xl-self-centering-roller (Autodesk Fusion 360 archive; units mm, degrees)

design "XL SELF CENTERING ROLLER" references "XL ROLLER"
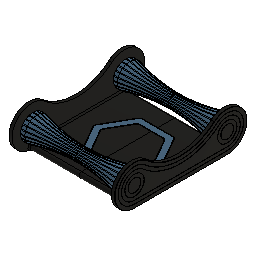
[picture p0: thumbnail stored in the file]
sketch "Sketch1" plane through (0, 0, 0) normal (1, 0, 0) x axis (0, 1, 0)
  line L1 (70, 4) -> (-70, 4)
  line L2 (70, -4) -> (70, 4)
  line L3 (-70, -4) -> (70, -4)
  line L4 (-70, 4) -> (-70, -4)
  line L5 (70, -4) -> (-70, 4)
  line L6 (-70, -4) -> (70, 4)
  line L7 (-104.641, 0) -> (-87.3205, 30)
  line L8 (-87.3205, -30) -> (-104.641, 0)
  line L9 (-52.6795, -30) -> (-87.3205, -30)
  line L10 (-35.359, 0) -> (-52.6795, -30)
  line L11 (-52.6795, 30) -> (-35.359, 0)
  line L12 (-87.3205, 30) -> (-52.6795, 30)
  line L13 (35.359, 0) -> (52.6795, 30)
  line L14 (52.6795, -30) -> (35.359, 0)
  line L15 (87.3205, -30) -> (52.6795, -30)
  line L16 (104.641, 0) -> (87.3205, -30)
  line L17 (87.3205, 30) -> (104.641, 0)
  line L18 (52.6795, 30) -> (87.3205, 30)
  line L19 (-52.6795, -30) -> (52.6795, -30)
  line L20 (35.359, 0) -> (-35.359, 0)
  line L21 (-82.7017, -22) -> (-87.3205, -30)
  line L22 (82.7017, -22) -> (-82.7017, -22)
  line L23 (87.3205, -30) -> (82.7017, -22)
  line L24 (-91.9393, -22) -> (91.9393, -22)
  line L25 (70, 0) -> (-70, 0)
  line L26 (0, -30) -> (0, 0)
  line L27 (0, -30) -> (0, -22)
  line L28 (-70, -22) -> (70, -22)
  line L29 (70, -30) -> (-70, -30)
  line L30 (70, -26) -> (70, 0)
  circle C1 centre (-70, 0) radius 4
  circle C2 centre (70, 0) radius 4
  circle C3 centre (70, 0) radius 5
  circle C4 centre (-70, 0) radius 5
  circle C5 centre (-70, 0) radius 30
  circle C6 centre (70, 0) radius 30
  arc A1 centre (-70, -26) radius 4 clockwise from (-70, -30) to (-70, -22)
  arc A2 centre (70, -26) radius 4 clockwise from (70, -22) to (70, -30)
  arc A3 centre (0, 81.2307) radius 77.2307 clockwise from (50.4161, 22.726) to (-50.4161, 22.726)
  point P6 (0, 0)
  point P1 (0, 0)
  point P7 (-70, 0)
  point P8 (70, 0)
  point P15 (-70, 0)
  point P22 (70, 0)
  point P27 (91.9393, -22)
  point P28 (-91.9393, -22)
  point P29 (-70, 0)
  point P31 (-70, 0)
  point P32 (70, 0)
  point P33 (0, 0)
  point P34 (0, -30)
  point P35 (0, -22)
  point P42 (0, -26)
  point P30 (70, 0)
  point P43 (70, 0)
  point P40 (70, -26)
  point P44 (70, -26)
  point P41 (-70, -26)
  point P46 (50.4161, 22.726)
  point P45 (-50.4161, 22.726)
  point P4 (70, -4)
  point P5 (-70, -4)
  horizontal L1
  perpendicular L1 L2
  parallel L1 L3
  parallel L2 L4
  coincident L5 P6
  coincident L6 P6
  coincident P1 P6
  midpoint L4 P7
  midpoint L2 P8
  tangent L1 C1
  coincident P7 P15
  coincident P8 P22
  horizontal L12
  horizontal L18
  parallel L15 L22
  parallel L17 L23
  parallel L7 L21
  coincident L16 P27
  coincident L8 P28
  parallel L22 L24
  collinear L22 L24
  concentric C1 C5
  tangent L9 C5
  concentric C2 C6
  tangent L15 C6
  coincident P29 P31
  coincident P22 P32
  coincident P6 P33
  midpoint L19 P34
  midpoint L24 P35
  tangent L28 A1
  tangent A1 L29
  parallel L28 L29
  tangent L29 A2
  tangent L28 A2
  midpoint L27 P42
  coincident P30 P43
  coincident P40 P44
  vertical L30
  collinear L22 L28
  collinear L19 L29
  vertical P29 P41
  coincident C6 P46
  coincident C5 P45
  tangent C5 A3
  tangent C6 A3
  tangent L1 A3
  dimension "d1" diameter C1 = 8 (= "d2")
  dimension "d2" diameter C2 = 8
  dimension "d3" distance P4 P5 = 140
  dimension "d4" distance L9 L12 = 60
  dimension "d5" distance L15 L18 = 60 (= "d4")
  dimension "d6" distance L19 L22 = 8
  dimension "d13" = 1
  dimension "d14" = 1
extrude "Extrude1" new body sketch "MirrorComponent3" profile of L9 L10 L14 L15 L19 L22 L24 C5 C6 L27 L28 A1 L29 A2 against normal blind 75
extrude "Extrude2" add sketch "MirrorComponent3" profile of L1 L2 L3 L4 C1 C2 L9 L10 L14 L15 L19 L20 L21 L22 L23 C3 C4 L24 C5 C6 L25 L27 L28 A1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 along normal blind 5
extrude "Extrude3" add sketch "MirrorComponent3" profile of L2 L4 C1 C2 against normal blind 6
extrude "Extrude19" add sketch "MirrorComponent3" profile of L1 L11 L13 L20 C5 C6 L25 A3 along normal blind 5
chamfer "Chamfer1" distance 0.6
sketch "Sketch2" plane through (5, 0, 0) normal (1, 0, 0) x axis (0, 1, 0)
  line L1 (63.8564, -25) -> (-63.8564, -25)
  line L2 (78.5788, -0.5) -> (64.7224, -24.5)
  line L3 (64.7224, 24.5) -> (78.5788, 0.5)
  line L4 (36.1436, 25) -> (63.8564, 25)
  line L5 (21.4212, 0.5) -> (35.2776, 24.5)
  line L6 (-20.5551, 0) -> (20.5551, 0)
  line L7 (-35.2776, 24.5) -> (-21.4212, 0.5)
  line L8 (-63.8564, 25) -> (-36.1436, 25)
  line L9 (-78.5788, 0.5) -> (-64.7224, 24.5)
  line L10 (-64.7224, -24.5) -> (-78.5788, -0.5)
  line L11 (-75.8653, 0) -> (-62.9326, 22.4)
  line L12 (-62.9326, -22.4) -> (-75.8653, 0)
  line L13 (-35.5662, -22.4) -> (-62.9326, -22.4)
  line L14 (62.9326, -22.4) -> (-35.5662, -22.4)
  line L15 (75.8653, 0) -> (62.9326, -22.4)
  line L16 (62.9326, 22.4) -> (75.8653, 0)
  line L17 (37.0674, 22.4) -> (62.9326, 22.4)
  line L18 (23.6728, -0.8) -> (37.0674, 22.4)
  line L19 (-20.5551, -2.6) -> (20.5551, -2.6)
  line L20 (-37.0674, 22.4) -> (-23.6728, -0.8)
  line L21 (-62.9326, 22.4) -> (-37.0674, 22.4)
  line L22 (-73.5559, 0) -> (-61.7779, 20.4)
  line L23 (-61.7779, -20.4) -> (-73.5559, 0)
  line L24 (-35.5662, -20.4) -> (-61.7779, -20.4)
  line L25 (61.7779, -20.4) -> (-35.5662, -20.4)
  line L26 (73.5559, 0) -> (61.7779, -20.4)
  line L27 (61.7779, 20.4) -> (73.5559, 0)
  line L28 (38.2221, 20.4) -> (61.7779, 20.4)
  line L29 (25.4049, -1.8) -> (38.2221, 20.4)
  line L30 (-20.5551, -4.6) -> (20.5551, -4.6)
  line L31 (-38.2221, 20.4) -> (-25.4049, -1.8)
  line L32 (-61.7779, 20.4) -> (-38.2221, 20.4)
  line L33 (70, -30) -> (-70, -30)
  arc A1 centre (-63.8564, -24) radius 1 clockwise from (-63.8564, -25) to (-64.7224, -24.5)
  arc A2 centre (63.8564, -24) radius 1 clockwise from (64.7224, -24.5) to (63.8564, -25)
  arc A3 centre (77.7128, 0) radius 1 clockwise from (78.5788, 0.5) to (78.5788, -0.5)
  arc A4 centre (63.8564, 24) radius 1 clockwise from (63.8564, 25) to (64.7224, 24.5)
  arc A5 centre (36.1436, 24) radius 1 clockwise from (35.2776, 24.5) to (36.1436, 25)
  arc A6 centre (20.5551, 1) radius 1 clockwise from (21.4212, 0.5) to (20.5551, 0)
  arc A7 centre (-20.5551, 1) radius 1 clockwise from (-20.5551, 0) to (-21.4212, 0.5)
  arc A8 centre (-36.1436, 24) radius 1 clockwise from (-36.1436, 25) to (-35.2776, 24.5)
  arc A9 centre (-63.8564, 24) radius 1 clockwise from (-64.7224, 24.5) to (-63.8564, 25)
  arc A10 centre (-77.7128, 0) radius 1 clockwise from (-78.5788, -0.5) to (-78.5788, 0.5)
  arc A11 centre (20.5551, 1) radius 3.6 clockwise from (23.6728, -0.8) to (20.5551, -2.6)
  arc A12 centre (-20.5551, 1) radius 3.6 clockwise from (-20.5551, -2.6) to (-23.6728, -0.8)
  arc A13 centre (20.5551, 1) radius 5.6 clockwise from (25.4049, -1.8) to (20.5551, -4.6)
  arc A14 centre (-20.5551, 1) radius 5.6 clockwise from (-20.5551, -4.6) to (-25.4049, -1.8)
  arc A15 centre (70, 0) radius 30 clockwise from (50.4161, 22.726) to (70, -30)
  arc A16 centre (-70, 0) radius 30 clockwise from (-70, -30) to (-50.4161, 22.726)
  arc A17 centre (0, 81.2307) radius 77.2307 clockwise from (50.4161, 22.726) to (-50.4161, 22.726)
  concentric A6 A11
  concentric A7 A12
  tangent A12 L20
  tangent L18 A11
  tangent A11 L19
  tangent L19 A12
  concentric A6 A13
  concentric A7 A14
  tangent A14 L31
  tangent A13 L30
  tangent L29 A13
  tangent L30 A14
sketch "Sketch3" plane through (0, 0, -22) normal (0, 0, 1) x axis (-1, 0, 0)
  line L1 (75, 70) -> (75, -70)
  line L2 (126.9615, 0) -> (100.9808, -45)
  line L3 (100.9808, 45) -> (126.9615, 0)
  line L4 (49.0192, 45) -> (100.9808, 45)
  line L5 (23.0385, 0) -> (49.0192, 45)
  line L6 (49.0192, -45) -> (23.0385, 0)
  line L7 (100.9808, -45) -> (49.0192, -45)
  line L8 (95.2073, 35) -> (115.4145, 0)
  line L9 (54.7927, 35) -> (95.2073, 35)
  line L10 (34.5855, 0) -> (54.7927, 35)
  line L11 (54.7927, -35) -> (34.5855, 0)
  line L12 (95.2073, -35) -> (54.7927, -35)
  line L13 (115.4145, 0) -> (95.2073, -35)
  line L14 (75, -70) -> (0, -70)
  line L15 (0, 70) -> (75, 70)
  line L16 (0, -70) -> (0, 70)
  point P12 (75, 0)
  midpoint L1 P12
  horizontal L7
  dimension "d23" distance L4 L7 = 90
  dimension "d24" = -10
extrude "Extrude5" cut sketch "Sketch3" profile of L1 L4 L5 L6 L7 L12 L10 L9 L11 against normal blind 2
fillet "Fillet2" radius 5
extrude "Extrude6" add sketch "MirrorComponent3" profile of L1 L3 C1 C2 C3 C4 against normal blind 1.4
chamfer "Chamfer3" distance 1.4
chamfer "Chamfer6" distance 0.4
chamfer "Chamfer10" distance 2
sketch "Sketch11" plane through (5, 0, 0) normal (1, 0, 0) x axis (0, 1, 0)
  line L1 (70, -29.6) -> (-70, -29.6)
  line L2 (70, -24.6) -> (-70, -24.6)
  line L3 (70, -19.6) -> (-70, -19.6)
  arc A1 centre (70, 0) radius 29.6 clockwise from (50.6772, 22.423) to (70, -29.6)
  arc A2 centre (0, 81.2307) radius 77.6307 clockwise from (50.6772, 22.423) to (-50.6772, 22.423)
  arc A3 centre (-70, 0) radius 29.6 clockwise from (-70, -29.6) to (-50.6772, 22.423)
  arc A4 centre (70, 0) radius 24.6 clockwise from (53.9412, 18.6353) to (70, -24.6)
  arc A5 centre (0, 81.2307) radius 82.6307 clockwise from (53.9412, 18.6353) to (-53.9412, 18.6353)
  arc A6 centre (-70, 0) radius 24.6 clockwise from (-70, -24.6) to (-53.9412, 18.6353)
  arc A7 centre (70, 0) radius 19.6 clockwise from (57.2052, 14.8476) to (70, -19.6)
  arc A8 centre (0, 81.2307) radius 87.6307 clockwise from (57.2052, 14.8476) to (-57.2052, 14.8476)
  arc A9 centre (-70, 0) radius 19.6 clockwise from (-70, -19.6) to (-57.2052, 14.8476)
  circle C1 centre (-70, 0) radius 14.6
  circle C2 centre (70, 0) radius 14.6
  circle C3 centre (-70, 0) radius 9.6
  circle C4 centre (70, 0) radius 9.6
  concentric A3 C1
  concentric A1 C2
  concentric C1 C3
  concentric C2 C4
  dimension "d145" = -5
  dimension "d146" = -10
  dimension "d148" distance A9 C1 = 5
  dimension "d149" distance A7 C2 = 5 (= "d148")
  dimension "d168" distance C1 C3 = 5
  dimension "d169" distance C2 C4 = 5
extrude "Extrude21" cut sketch "Sketch11" profile of L2 A6 A5 A4 L3 A9 A8 A7 C1 C2 C3 C4 against normal blind 0.4
mirror "Mirror1" mirrorStitchTolerance 0.1
sketch "Sketch1" plane through (0, 0, -24) normal (0, 0, 1) x axis (-1, 0, 0)
  line L1 (98.094, -45) -> (51.906, -45)
  line L2 (57.6795, -35) -> (92.3205, -35)
  line L3 (36.0289, -2.5) -> (53.3494, -32.5)
  line L4 (53.3494, 32.5) -> (36.0289, 2.5)
  line L5 (92.3205, 35) -> (57.6795, 35)
  line L6 (51.906, 45) -> (98.094, 45)
  line L7 (24.4819, 2.5) -> (47.5759, 42.5)
  line L8 (47.5759, -42.5) -> (24.4819, -2.5)
  line L9 (125.5181, -2.5) -> (102.4241, -42.5)
  line L10 (102.4241, 42.5) -> (125.5181, 2.5)
  line L11 (113.9711, 2.5) -> (96.6506, 32.5)
  line L12 (96.6506, -32.5) -> (113.9711, -2.5)
  line L13 (51.906, 45) -> (98.094, 45)
  line L14 (24.4819, 2.5) -> (47.5759, 42.5)
  line L15 (47.5759, -42.5) -> (24.4819, -2.5)
  line L16 (98.094, -45) -> (51.906, -45)
  line L17 (125.5181, -2.5) -> (102.4241, -42.5)
  line L18 (102.4241, 42.5) -> (125.5181, 2.5)
  line L19 (92.3205, 35) -> (57.6795, 35)
  line L20 (113.9711, 2.5) -> (96.6506, 32.5)
  line L21 (96.6506, -32.5) -> (113.9711, -2.5)
  line L22 (57.6795, -35) -> (92.3205, -35)
  line L23 (36.0289, -2.5) -> (53.3494, -32.5)
  line L24 (53.3494, 32.5) -> (36.0289, 2.5)
  line L25 (24.6551, 2.4) -> (47.7491, 42.4)
  line L26 (47.7491, -42.4) -> (24.6551, -2.4)
  line L27 (98.094, -44.8) -> (51.906, -44.8)
  line L28 (125.3449, -2.4) -> (102.2509, -42.4)
  line L29 (102.2509, 42.4) -> (125.3449, 2.4)
  line L30 (51.906, 44.8) -> (98.094, 44.8)
  line L31 (92.3205, 35.2) -> (57.6795, 35.2)
  line L32 (53.1762, 32.6) -> (35.8557, 2.6)
  line L33 (35.8557, -2.6) -> (53.1762, -32.6)
  line L34 (57.6795, -35.2) -> (92.3205, -35.2)
  line L35 (96.8238, -32.6) -> (114.1443, -2.6)
  line L36 (114.1443, 2.6) -> (96.8238, 32.6)
  line L37 (121.188, 0) -> (98.094, -40)
  line L38 (98.094, 40) -> (121.188, 0)
  line L39 (51.906, 40) -> (98.094, 40)
  line L40 (28.812, 0) -> (51.906, 40)
  line L41 (51.906, -40) -> (28.812, 0)
  line L42 (98.094, -40) -> (51.906, -40)
  arc A1 centre (51.906, -40) radius 5 clockwise from (51.906, -45) to (47.5759, -42.5)
  arc A2 centre (57.6795, -30) radius 5 clockwise from (57.6795, -35) to (53.3494, -32.5)
  arc A3 centre (40.359, 0) radius 5 clockwise from (36.0289, -2.5) to (36.0289, 2.5)
  arc A4 centre (57.6795, 30) radius 5 clockwise from (53.3494, 32.5) to (57.6795, 35)
  arc A5 centre (51.906, 40) radius 5 clockwise from (47.5759, 42.5) to (51.906, 45)
  arc A6 centre (28.812, 0) radius 5 clockwise from (24.4819, -2.5) to (24.4819, 2.5)
  arc A7 centre (98.094, -40) radius 5 clockwise from (102.4241, -42.5) to (98.094, -45)
  arc A8 centre (121.188, 0) radius 5 clockwise from (125.5181, 2.5) to (125.5181, -2.5)
  arc A9 centre (98.094, 40) radius 5 clockwise from (98.094, 45) to (102.4241, 42.5)
  arc A10 centre (92.3205, 30) radius 5 clockwise from (92.3205, 35) to (96.6506, 32.5)
  arc A11 centre (109.641, 0) radius 5 clockwise from (113.9711, 2.5) to (113.9711, -2.5)
  arc A12 centre (92.3205, -30) radius 5 clockwise from (96.6506, -32.5) to (92.3205, -35)
  arc A13 centre (51.906, 40) radius 5 clockwise from (47.5759, 42.5) to (51.906, 45)
  arc A14 centre (28.812, 0) radius 5 clockwise from (24.4819, -2.5) to (24.4819, 2.5)
  arc A15 centre (51.906, -40) radius 5 clockwise from (51.906, -45) to (47.5759, -42.5)
  arc A16 centre (98.094, -40) radius 5 clockwise from (102.4241, -42.5) to (98.094, -45)
  arc A17 centre (121.188, 0) radius 5 clockwise from (125.5181, 2.5) to (125.5181, -2.5)
  arc A18 centre (98.094, 40) radius 5 clockwise from (98.094, 45) to (102.4241, 42.5)
  arc A19 centre (92.3205, 30) radius 5 clockwise from (92.3205, 35) to (96.6506, 32.5)
  arc A20 centre (109.641, 0) radius 5 clockwise from (113.9711, 2.5) to (113.9711, -2.5)
  arc A21 centre (92.3205, -30) radius 5 clockwise from (96.6506, -32.5) to (92.3205, -35)
  arc A22 centre (57.6795, -30) radius 5 clockwise from (57.6795, -35) to (53.3494, -32.5)
  arc A23 centre (40.359, 0) radius 5 clockwise from (36.0289, -2.5) to (36.0289, 2.5)
  arc A24 centre (57.6795, 30) radius 5 clockwise from (53.3494, 32.5) to (57.6795, 35)
  arc A25 centre (28.812, 0) radius 4.8 clockwise from (24.6551, -2.4) to (24.6551, 2.4)
  arc A26 centre (51.906, -40) radius 4.8 clockwise from (51.906, -44.8) to (47.7491, -42.4)
  arc A27 centre (98.094, -40) radius 4.8 clockwise from (102.2509, -42.4) to (98.094, -44.8)
  arc A28 centre (121.188, 0) radius 4.8 clockwise from (125.3449, 2.4) to (125.3449, -2.4)
  arc A29 centre (98.094, 40) radius 4.8 clockwise from (98.094, 44.8) to (102.2509, 42.4)
  arc A30 centre (51.906, 40) radius 4.8 clockwise from (47.7491, 42.4) to (51.906, 44.8)
  arc A31 centre (92.3205, 30) radius 5.2 clockwise from (92.3205, 35.2) to (96.8238, 32.6)
  arc A32 centre (57.6795, 30) radius 5.2 clockwise from (53.1762, 32.6) to (57.6795, 35.2)
  arc A33 centre (40.359, 0) radius 5.2 clockwise from (35.8557, -2.6) to (35.8557, 2.6)
  arc A34 centre (57.6795, -30) radius 5.2 clockwise from (57.6795, -35.2) to (53.1762, -32.6)
  arc A35 centre (92.3205, -30) radius 5.2 clockwise from (96.8238, -32.6) to (92.3205, -35.2)
  arc A36 centre (109.641, 0) radius 5.2 clockwise from (114.1443, 2.6) to (114.1443, -2.6)
  circle C1 centre (40.359, -20) radius 2.5
  circle C2 centre (40.359, 20) radius 2.5
  circle C3 centre (109.641, -20) radius 2.5
  circle C4 centre (109.641, 20) radius 2.5
  circle C5 centre (40.359, -20) radius 2.3
  circle C6 centre (40.359, 20) radius 2.3
  circle C7 centre (109.641, 20) radius 2.3
  circle C8 centre (109.641, -20) radius 2.3
  point P116 (40.359, -20)
  point P117 (40.359, 20)
  point P118 (109.641, -20)
  point P119 (109.641, 20)
  midpoint L41 P116
  midpoint L40 P117
  coincident L37 P118
  midpoint L38 P119
  midpoint L37 P118
  concentric C1 C5
  concentric C2 C6
  concentric C4 C7
  concentric C3 C8
  dimension "d37" = -0.2
  dimension "d38" = -0.2
  dimension "d53" = -5
  dimension "d54" diameter C1 = 5
  dimension "d55" diameter C3 = 5 (= "d54")
  dimension "d56" diameter C2 = 5 (= "d54")
  dimension "d57" diameter C4 = 5 (= "d54")
  dimension "d90" diameter C5 = 4.6
  dimension "d91" diameter C8 = 4.6 (= "d90")
  dimension "d92" diameter C6 = 4.6 (= "d90")
  dimension "d93" diameter C7 = 4.6 (= "d90")
extrude "Extrude7" new body sketch "Sketch1" profile of A30 L27 A28 L28 A27 L25 A26 L30 L29 L26 A29 A25 A36 L32 A35 L35 A34 L33 L36 A33 A32 L31 L34 A31 along normal blind 2
work_plane "WorkPlane1"
split "Split1" bodies "SIDE B"
chamfer "Chamfer4" distance 0.6
extrude "Extrude8" cut sketch "Sketch1" profile of L38 L41 L40 L37 C1 C2 C3 C4 C5 C6 C7 C8 no distance stored
extrude "Extrude9" add sketch "Sketch1" profile of L38 L41 L40 L37 C1 C2 C3 C4 C5 C6 C7 C8 to an object
extrude "Extrude14" sketch "Sketch1" profile of L38 L41 L40 L37 C1 C2 C3 C4 C5 C6 C7 C8 blind -1 from offset -2.5
extrude "Extrude16" cut of existing geometry blind -0.2
chamfer "Chamfer7" distance 0.2
chamfer "Chamfer5" distance 0.4
sketch "Sketch5" plane through (0, 0, -24) normal (0, 0, 1) x axis (-1, 0, 0)
  line L1 (75, -35) -> (75, -45)
  line L2 (57.6795, -35) -> (75, -35)
  line L3 (36.0289, -2.5) -> (53.3494, -32.5)
  line L4 (53.3494, 32.5) -> (36.0289, 2.5)
  line L5 (75, 35) -> (57.6795, 35)
  line L6 (75, 45) -> (75, 35)
  line L7 (51.906, 45) -> (75, 45)
  line L8 (24.4819, 2.5) -> (47.5759, 42.5)
  line L9 (47.5759, -42.5) -> (24.4819, -2.5)
  line L10 (75, -45) -> (51.906, -45)
  line L11 (71, -40) -> (75, -40)
  line L12 (71, 40) -> (75, 40)
  line L13 (67, 39) -> (75, 39)
  line L14 (67, 41) -> (67, 39)
  line L15 (75, 41) -> (67, 41)
  line L16 (75, 39) -> (75, 41)
  line L17 (67, 41) -> (75, 39)
  line L18 (75, 41) -> (67, 39)
  line L19 (67, -41) -> (75, -41)
  line L20 (67, -39) -> (67, -41)
  line L21 (75, -39) -> (67, -39)
  line L22 (75, -41) -> (75, -39)
  line L23 (67, -39) -> (75, -41)
  line L24 (75, -39) -> (67, -41)
  circle C1 centre (40.359, -20) radius 2.5
  circle C2 centre (40.359, 20) radius 2.5
  arc A1 centre (57.6795, -30) radius 5 clockwise from (57.6795, -35) to (53.3494, -32.5)
  arc A2 centre (40.359, 0) radius 5 clockwise from (36.0289, -2.5) to (36.0289, 2.5)
  arc A3 centre (57.6795, 30) radius 5 clockwise from (53.3494, 32.5) to (57.6795, 35)
  arc A4 centre (51.906, 40) radius 5 clockwise from (47.5759, 42.5) to (51.906, 45)
  arc A5 centre (28.812, 0) radius 5 clockwise from (24.4819, -2.5) to (24.4819, 2.5)
  arc A6 centre (51.906, -40) radius 5 clockwise from (51.906, -45) to (47.5759, -42.5)
  circle C3 centre (71, 40) radius 2
  circle C4 centre (71, -40) radius 2
  point P26 (75, -40)
  point P28 (75, 40)
  point P29 (71, 40)
  point P30 (71, 40)
  point P35 (71, 40)
  point P31 (75, 39)
  point P27 (71, -40)
  point P36 (71, -40)
  point P41 (71, -40)
  point P37 (75, -41)
  point P38 (67, -41)
  point P39 (67, -39)
  midpoint L1 P26
  perpendicular L1 L11
  midpoint L6 P28
  perpendicular L6 L12
  coincident P29 P30
  horizontal L13
  perpendicular L13 L14
  parallel L13 L15
  parallel L14 L16
  coincident L17 P35
  coincident L18 P35
  coincident L6 P31
  coincident P30 P35
  coincident P27 P36
  horizontal L19
  perpendicular L19 L20
  parallel L19 L21
  parallel L20 L22
  coincident L23 P41
  coincident L24 P41
  coincident L1 P37
  coincident P36 P41
  dimension "d73" diameter C3 = 4
  dimension "d74" distance L13 L15 = 2
  dimension "d75" distance P28 P29 = 4
  dimension "d76" diameter C4 = 4 (= "d73")
  dimension "d77" distance P37 P38 = 8
  dimension "d78" distance P38 P39 = 2
offset_faces "OffsetFaces2" distance -0.1
combine "Combine1"
offset_faces "OffsetFaces3" distance -0.05
sketch "Sketch8" plane through (0, 0, -29.8) normal (0, 0, -1) x axis (1, 0, 0)
  circle C1 centre (-83.9808, -15) radius 1.8
  circle C2 centre (-32.0192, -15) radius 1.5
  circle C3 centre (-32.0192, 15) radius 1.5
  circle C4 centre (-83.9808, 15) radius 1.5
  circle C5 centre (-83.9808, -15) radius 1.5
  circle C6 centre (-40.359, -20) radius 2
  point P5 (-83.9808, 15)
  point P7 (-83.9808, 15)
  point P4 (-32.0192, 15)
  point P8 (-32.0192, 15)
  point P3 (-32.0192, -15)
  point P9 (-32.0192, -15)
  concentric C1 C5
  coincident P5 P7
  coincident P4 P8
  coincident P3 P9
  dimension "d100" diameter C5 = 3
  dimension "d101" diameter C4 = 3 (= "d100")
  dimension "d102" diameter C3 = 3 (= "d101")
  dimension "d103" diameter C2 = 3 (= "d101")
sketch "Sketch9" plane through (-75, 0, 0) normal (1, 0, 0) x axis (0, 1, 0)
  line L1 (35, -24) -> (45, -24)
  line L2 (-45, -22) -> (-45, -24)
  line L3 (-70, -22) -> (-45, -22)
  line L4 (70, -30) -> (-70, -30)
  line L5 (45, -22) -> (70, -22)
  line L6 (45, -24) -> (45, -22)
  line L7 (35, -22) -> (35, -24)
  line L8 (-35, -22) -> (35, -22)
  line L9 (-35, -24) -> (-35, -22)
  line L10 (74, -26) -> (-74, -26)
  line L11 (-61.5, -27) -> (-66.5, -27)
  line L12 (-66.5, -25) -> (-61.5, -25)
  line L13 (-61.5, -26) -> (-66.5, -26)
  line L14 (2.5, -27) -> (-2.5, -27)
  line L15 (-2.5, -25) -> (2.5, -25)
  line L16 (2.5, -26) -> (-2.5, -26)
  line L17 (66.5, -27) -> (61.5, -27)
  line L18 (61.5, -25) -> (66.5, -25)
  line L19 (66.5, -26) -> (61.5, -26)
  line L20 (-45, -24) -> (-35, -24)
  arc A1 centre (-70, -26) radius 4 clockwise from (-70, -30) to (-70, -22)
  arc A2 centre (70, -26) radius 4 clockwise from (70, -22) to (70, -30)
  circle C1 centre (-64, -26) radius 0.9
  circle C2 centre (0, -26) radius 0.9
  circle C3 centre (64, -26) radius 0.9
  arc A3 centre (-61.5, -26) radius 1 clockwise from (-61.5, -25) to (-61.5, -27)
  arc A4 centre (-66.5, -26) radius 1 clockwise from (-66.5, -27) to (-66.5, -25)
  arc A5 centre (2.5, -26) radius 1 clockwise from (2.5, -25) to (2.5, -27)
  arc A6 centre (-2.5, -26) radius 1 clockwise from (-2.5, -27) to (-2.5, -25)
  arc A7 centre (66.5, -26) radius 1 clockwise from (66.5, -25) to (66.5, -27)
  arc A8 centre (61.5, -26) radius 1 clockwise from (61.5, -27) to (61.5, -25)
  point P20 (-74, -26)
  point P21 (74, -26)
  point P19 (64, -26)
  point P18 (0, -26)
  point P17 (-64, -26)
  point P27 (-61.5, -26)
  point P28 (-64, -26)
  point P34 (2.5, -26)
  point P35 (0, -26)
  point P41 (66.5, -26)
  point P42 (64, -26)
  point P26 (-66.5, -26)
  point P40 (61.5, -26)
  point P33 (-2.5, -26)
  midpoint A1 P20
  midpoint A2 P21
  coincident P19 L10
  coincident P18 L10
  coincident P17 L10
  midpoint P18 L10
  tangent L11 A3
  tangent A3 L12
  parallel L11 L12
  tangent L12 A4
  tangent L11 A4
  coincident L10 P27
  parallel L10 L13
  coincident P17 P28
  midpoint L13 P28
  tangent L14 A5
  tangent A5 L15
  parallel L14 L15
  tangent L15 A6
  tangent L14 A6
  coincident L10 P34
  parallel L10 L16
  coincident P18 P35
  midpoint L16 P35
  tangent L17 A7
  tangent A7 L18
  parallel L17 L18
  tangent L18 A8
  tangent L17 A8
  coincident L10 P41
  parallel L10 L19
  coincident P19 P42
  midpoint L19 P42
  dimension "d108" diameter C1 = 1.8
  dimension "d109" diameter C2 = 1.8
  dimension "d110" diameter C3 = 1.8
  dimension "d111" distance P17 P20 = 10
  dimension "d112" distance P19 P21 = 10
  dimension "d115" distance L11 L12 = 2
  dimension "d116" distance P26 P27 = 5
  dimension "d117" distance P40 P41 = 5
  dimension "d118" distance L17 L18 = 2 (= "d115")
  dimension "d119" distance L14 L15 = 2 (= "d115")
  dimension "d120" distance P33 P34 = 5
extrude "Extrude17" cut sketch "Sketch9" profile of C1 C2 C3 L10 L11 A3 L12 A4 L14 A5 L15 A6 L17 A7 L18 A8 distance -20
sketch "Sketch10" plane through (-75, 0, 0) normal (1, 0, 0) x axis (0, 1, 0)
  line L1 (2.5, -27) -> (-2.5, -27)
  line L2 (-2.5, -25) -> (2.5, -25)
  line L3 (66.5, -27) -> (61.5, -27)
  line L4 (61.5, -25) -> (66.5, -25)
  line L5 (-61.5, -27) -> (-66.5, -27)
  line L6 (-66.5, -25) -> (-61.5, -25)
  line L7 (-45, -24) -> (-45, -22)
  line L8 (-35, -24) -> (-45, -24)
  line L9 (-35, -22) -> (-35, -24)
  line L10 (35, -22) -> (-35, -22)
  line L11 (35, -24) -> (35, -22)
  line L12 (45, -24) -> (35, -24)
  line L13 (45, -22) -> (45, -24)
  line L14 (70, -22) -> (45, -22)
  line L15 (-70, -30) -> (70, -30)
  line L16 (-45, -22) -> (-70, -22)
  line L17 (66.5, -26.8) -> (61.5, -26.8)
  line L18 (61.5, -25.2) -> (66.5, -25.2)
  line L19 (-2.5, -25.2) -> (2.5, -25.2)
  line L20 (2.5, -26.8) -> (-2.5, -26.8)
  line L21 (-66.5, -25.2) -> (-61.5, -25.2)
  line L22 (-61.5, -26.8) -> (-66.5, -26.8)
  arc A1 centre (2.5, -26) radius 1 clockwise from (2.5, -25) to (2.5, -27)
  arc A2 centre (-2.5, -26) radius 1 clockwise from (-2.5, -27) to (-2.5, -25)
  arc A3 centre (66.5, -26) radius 1 clockwise from (66.5, -25) to (66.5, -27)
  arc A4 centre (61.5, -26) radius 1 clockwise from (61.5, -27) to (61.5, -25)
  arc A5 centre (-61.5, -26) radius 1 clockwise from (-61.5, -25) to (-61.5, -27)
  arc A6 centre (-66.5, -26) radius 1 clockwise from (-66.5, -27) to (-66.5, -25)
  arc A7 centre (70, -26) radius 4 clockwise from (70, -22) to (70, -30)
  arc A8 centre (-70, -26) radius 4 clockwise from (-70, -30) to (-70, -22)
  arc A9 centre (66.5, -26) radius 0.8 clockwise from (66.5, -25.2) to (66.5, -26.8)
  arc A10 centre (61.5, -26) radius 0.8 clockwise from (61.5, -26.8) to (61.5, -25.2)
  arc A11 centre (2.5, -26) radius 0.8 clockwise from (2.5, -25.2) to (2.5, -26.8)
  arc A12 centre (-2.5, -26) radius 0.8 clockwise from (-2.5, -26.8) to (-2.5, -25.2)
  arc A13 centre (-66.5, -26) radius 0.8 clockwise from (-66.5, -26.8) to (-66.5, -25.2)
  arc A14 centre (-61.5, -26) radius 0.8 clockwise from (-61.5, -25.2) to (-61.5, -26.8)
  dimension "d130" = -0.2 (= "d132")
  dimension "d131" = -0.2 (= "d132")
  dimension "d132" = -0.2
extrude "Extrude18" new body sketch "Sketch10" profile of A14 A13 L22 L21 distance -19 bodies "INTERNAL SUPPORT"
chamfer "Chamfer8" distance 0.5
chamfer "Chamfer9" distance 0.6
rectangular_pattern "R-Pattern1" uSpaceDistance -128 vSpaceDistance 0 bodies "INTERNAL SUPPORT (1)", "INTERNAL SUPPORT (2)"
component_insert "Component Insert"
joint "Assemble4" alignAngle 0 alignOffsetX 0 alignOffsetY 0 alignOffsetZ 0
mirror_component "MirrorComponent3"
derived_instance "DerivedInstance3"
derived_instance "DerivedInstance2"
place_component sketch "Sketch1"
sketch "Sketch1" plane through (0, 0, 0) normal (1, 0, 0) x axis (0, 1, 0)
  circle C1 centre (101.4653, 185.2723) radius 125
  dimension "d152" diameter C1 = 250
extrude "Extrude1" new body sketch "Sketch1" against normal blind 120
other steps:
derived_base_feature "Derived Base Feature1"
derived_base_feature "Derived Base Feature1" bodies "SIDE A (1)"
create_component "CreateComponent3"
joint_origin "JointOrigin5"
create_component "CreateComponent9"
create_component "CreateComponent10" sketch "Sketch1"
create_component "CreateComponent11"
named bodies: "XL_side_roller (x2)", "XL_hex_insert (x1)", "SIDE B", "INTERNAL SUPPORT", "INTERNAL SUPPORT (1)", "INTERNAL SUPPORT (2)", "SIDE A (1)"

design "XL ROLLER" references "Bearing"
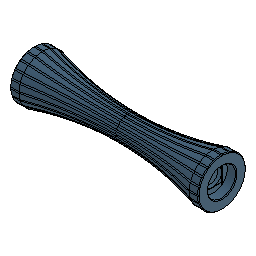
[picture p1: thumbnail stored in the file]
sketch "Sketch2" plane through (0, 0, 0) normal (0, 0, 1) x axis (1, 0, 0)
  line L1 (67, 18.75) -> (-67, 18.75)
  line L2 (67, -18.75) -> (67, 18.75)
  line L3 (-67, -18.75) -> (67, -18.75)
  line L4 (-67, 18.75) -> (-67, -18.75)
  line L5 (67, -18.75) -> (-67, 18.75)
  line L6 (-67, -18.75) -> (67, 18.75)
  line L7 (-74, 18.75) -> (-67, 18.75)
  line L8 (-74, 11.05) -> (-74, 18.75)
  line L9 (-67, 11.05) -> (-74, 11.05)
  line L10 (-67, 18.75) -> (-67, 11.05)
  line L11 (-67, 0) -> (0, 0)
  line L12 (67, 0) -> (-67, 0)
  line L13 (0, 18.75) -> (0, 0)
  line L14 (-65, 0) -> (-67, 0)
  line L15 (-65, 7) -> (-65, 0)
  line L16 (-67, 7) -> (-65, 7)
  line L17 (-67, 0) -> (-67, 7)
  arc A1 centre (0, 259.6047) radius 250 clockwise from (67, 18.75) to (-67, 18.75)
  point P6 (0, 0)
  point P1 (0, 0)
  point P10 (0, 0)
  point P11 (-67, 0)
  point P13 (67, 0)
  point P14 (0, 0)
  point P15 (0, 18.75)
  point P2 (-67, 18.75)
  point P7 (-74, 18.75)
  point P16 (-65, 0)
  point P17 (-65, 7)
  point P18 (-67, 7)
  horizontal L1
  perpendicular L1 L2
  parallel L1 L3
  parallel L2 L4
  coincident L5 P6
  coincident L6 P6
  coincident P1 P6
  horizontal L7
  vertical L8
  horizontal L9
  vertical L10
  coincident P6 P10
  midpoint L4 P11
  midpoint L2 P13
  coincident P1 P14
  midpoint L1 P15
  horizontal L14
  vertical L15
  horizontal L16
  vertical L17
  dimension "d2" distance P10 P11 = 67
  dimension "d3" distance L9 P11 = 11.05
  dimension "d4" distance L1 L3 = 37.5
  dimension "d5" radius A1 = 250
  dimension "d6" distance P2 P7 = 7
  dimension "d26" distance P16 P17 = 7
  dimension "d27" distance P17 P18 = 2
revolve "Revolve1" sketch "Sketch2" AlongAngle 360 bodies "old"
mirror "Mirror1" mirrorStitchTolerance 0.1
component_insert "Component Insert1"
joint "Assemble1" alignAngle 0 alignOffsetX 0 alignOffsetY 0 alignOffsetZ 0
component_insert "Component Insert2"
joint "Assemble2" alignAngle 0 alignOffsetX 0 alignOffsetY 0 alignOffsetZ 0
chamfer "Chamfer1" distance 0.6
sketch "Sketch3" plane through (67, 0, 0) normal (1, 0, 0) x axis (0, 1, 0)
  line L1 (7, -8.55) -> (-7, -8.55)
  line L2 (7, 8.55) -> (7, -8.55)
  line L3 (-7, 8.55) -> (7, 8.55)
  line L4 (-7, -8.55) -> (-7, 8.55)
  line L5 (7, 8.55) -> (-7, -8.55)
  line L6 (-7, 8.55) -> (7, -8.55)
  line L7 (8.55, -7) -> (-8.55, -7)
  line L8 (8.55, 7) -> (8.55, -7)
  line L9 (-8.55, 7) -> (8.55, 7)
  line L10 (-8.55, -7) -> (-8.55, 7)
  line L11 (8.55, 7) -> (-8.55, -7)
  line L12 (-8.55, 7) -> (8.55, -7)
  circle C1 centre (0, 0) radius 7
  circle C2 centre (0, 0) radius 11.05
  circle C3 centre (0, 0) radius 7
  point P7 (0, 0)
  point P3 (-7, -8.55)
  point P2 (0, 0)
  point P12 (0, 0)
  point P8 (-8.55, -7)
  horizontal L1
  perpendicular L1 L2
  parallel L1 L3
  parallel L2 L4
  coincident L5 P7
  coincident L6 P7
  coincident C2 P3
  coincident P2 P7
  horizontal L7
  perpendicular L7 L8
  parallel L7 L9
  parallel L8 L10
  coincident L11 P12
  coincident L12 P12
  coincident C2 P8
  coincident P7 P12
  tangent C1 L2
  tangent L7 C3
extrude "Extrude2" cut sketch "Sketch3" profile of C1 C2 L1 L2 L3 L4 L7 L9 C3 against normal blind 0.2
extrude "Extrude3" cut sketch "Sketch3" profile of C1 L2 L4 L7 L9 C3 against normal blind 0.4
chamfer "Chamfer2" distance 1.6
split "Split1" bodies "SIDE A"
sketch "Sketch1" plane through (0, 0, 0) normal (1, 0, 0) x axis (0, 1, 0)
  line L1 (5.7735, 0) -> (2.8868, -5)
  line L2 (2.8868, 5) -> (5.7735, 0)
  line L3 (-2.8868, 5) -> (2.8868, 5)
  line L4 (-5.7735, 0) -> (-2.8868, 5)
  line L5 (-2.8868, -5) -> (-5.7735, 0)
  line L6 (2.8868, -5) -> (-2.8868, -5)
  line L7 (2.829, 4.9) -> (5.658, 0)
  line L8 (-2.829, 4.9) -> (2.829, 4.9)
  line L9 (-5.658, 0) -> (-2.829, 4.9)
  line L10 (-2.829, -4.9) -> (-5.658, 0)
  line L11 (2.829, -4.9) -> (-2.829, -4.9)
  line L12 (5.658, 0) -> (2.829, -4.9)
  point P1 (0, 0)
  point P8 (0, 0)
  coincident P1 P8
  horizontal L6
  dimension "d19" distance L1 L4 = 10
  dimension "d20" = -0.1
extrude "Extrude1" cut sketch "Sketch1" distance -30
extrude "Extrude1" new body sketch "Sketch1" profile of L12 L11 L10 L9 L8 L7 distance 29
chamfer "Chamfer1" distance 0.6
ground "Ground1"
component_from_bodies "Body->Comp"
as_built_joint "As-built1"
sketch "Sketch2" plane through (0, 0, 0) normal (0, 1, 0) x axis (1, 0, 0)
  line L1 (67, 18.75) -> (67, -18.75)
  line L2 (0, 9.6047) -> (0, -9.6047)
  line L3 (67, 18.75) -> (67, -18.75)
  line L4 (73.4, 18.75) -> (73.4, -18.75)
  line L5 (73.4, 18.75) -> (73.4, -18.75)
  line L6 (74, -18.15) -> (74, 18.15)
  line L7 (-67, -18.75) -> (-73.4, -18.75)
  line L8 (-73.4, 18.75) -> (-67, 18.75)
  line L9 (-74, 18.15) -> (-73.4, 18.75)
  line L10 (-73.4, -18.75) -> (-74, -18.15)
  line L11 (73.4, 18.75) -> (74, 18.15)
  line L12 (74, -18.15) -> (73.4, -18.75)
  line L13 (73.4, -18.75) -> (67, -18.75)
  line L14 (67, 18.75) -> (73.4, 18.75)
  line L15 (78.4, -18.75) -> (73.4, -18.75)
  line L16 (-78.4, -18.75) -> (-73.4, -18.75)
  arc A1 centre (0, -259.6047) radius 250 between (67, -18.75) and (0, -9.6047)
  arc A2 centre (0, 259.6047) radius 250 between (0, 9.6047) and (67, 18.75)
  arc A3 centre (0, -259.6047) radius 250 between (0, -9.6047) and (-67, -18.75)
  arc A4 centre (0, 259.6047) radius 250 between (-67, 18.75) and (0, 9.6047)
  point P8 (73.4, -18.75)
  point P42 (73.4, -18.75)
  point P33 (-73.4, -18.75)
  point P44 (-73.4, -18.75)
  point P43 (78.4, -18.75)
  point P45 (-78.4, -18.75)
  coincident P8 P42
  perpendicular L4 L15
  coincident P33 P44
  parallel L7 L16
  dimension "d29" distance P42 P43 = 5
  dimension "d40" distance P44 P45 = 5 (= "d29")
pipe "Pipe1" SectionSize 1.2 SectionThickness 0.3
circular_pattern "C-Pattern1" countU 20 TotalAngle 360
mirror "Mirror2" mirrorStitchTolerance 0.1 bodies "SIDE A (1)"
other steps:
base_feature "Base Feature"
create_component "CreateComponent1"
joint_origin "JointOrigin1"
joint_origin "JointOrigin2"
create_component "CreateComponent3"
remove_body "RemoveBody1"
named bodies: "old", "SIDE A", "SIDE A (1)"

design "Bearing"
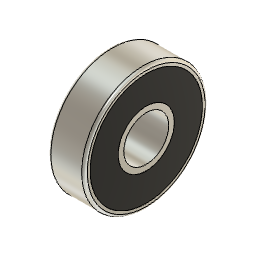
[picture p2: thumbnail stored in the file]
base_feature "Base Feature"
sketch "Sketch1" plane through (11, 0, 0) normal (1, 0, 0) x axis (0, 0, -1)
  circle C1 centre (0, 111) radius 4
  circle C2 centre (0, 111) radius 5
  circle C3 centre (0, 111) radius 4
  circle C4 centre (0, 111) radius 11
  concentric C1 C3
  concentric C3 C4
  dimension "d121" diameter C4 = 22
  dimension "d122" diameter C3 = 8
extrude "Extrude1" new body sketch "Sketch1" along normal blind 6.5
fillet "Fillet1" radius 0.5
sketch "Sketch2" plane through (17.5, 0, 0) normal (1, 0, 0) x axis (0, 1, 0)
  circle C1 centre (111, 0) radius 4
  circle C2 centre (111, 0) radius 10.5
  circle C3 centre (111, 0) radius 10
  circle C4 centre (111, 0) radius 5
  concentric C1 C3
  concentric C3 C4
  dimension "d3" distance C1 C4 = 1
  dimension "d4" distance C2 C3 = 0.5
extrude "Extrude2" cut sketch "Sketch2" profile of C3 C4 against normal blind 6.5
extrude "Extrude3" new body sketch "Sketch2" profile of C3 C4 against normal blind 6.5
